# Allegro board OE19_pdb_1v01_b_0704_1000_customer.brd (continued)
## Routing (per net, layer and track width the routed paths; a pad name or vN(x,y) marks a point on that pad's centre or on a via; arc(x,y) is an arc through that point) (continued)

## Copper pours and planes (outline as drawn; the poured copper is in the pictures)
GND on TOP (solid shape): 104.33,152.48 50.66,152.48 50.66,152.99 104.33,152.99
GND on TOP (solid shape): 157.33,152.48 114.59,152.48 114.59,152.99 157.33,152.99
GND on TOP (solid shape): 21.02,58 20.43,56.57 19,55.98 2,55.98 1.3,55.7 1.02,55 1.02,18.22 0.51,18.22 0.51,55 0.94,56.05 2,56.49 19,56.49 20.07,56.93 20.51,58 20.51,106.37 21.02,106.37
GND on TOP (solid shape): 41.02,134.5 40.42,133.07 39,132.48 22,132.48 21.3,132.2 21.02,131.5 21.02,115.91 20.51,115.91 20.51,131.5 20.94,132.56 22,132.99 39,132.99 40.07,133.43 40.51,134.5 40.51,147.73 41.02,147.73
GND on TOP (solid shape): 199.5,152.99 199.85,152.85 199.99,152.5 199.99,151.5 200.43,150.43 201.5,149.99 205.5,149.99 206.55,149.56 206.99,148.5 206.99,126.5 206.55,125.44 205.5,125.01 196.5,125.01 195.43,124.57 194.99,123.5 194.99,2 194.55,0.94 193.5,0.51 193.42,0.51 193.42,1.02 193.5,1.02 194.2,1.3 194.48,2 194.48,123.5 195.07,124.93 196.5,125.52 205.5,125.52 206.2,125.8 206.48,126.5 206.48,148.5 206.2,149.2 205.5,149.48 201.5,149.48 200.07,150.07 199.48,151.5 199.48,152.48 167.68,152.48 167.68,152.99
GND on BOTTOM (solid shape): 104.33,152.48 68.44,152.48 68.44,152.99 104.33,152.99
GND on BOTTOM (solid shape): 157.33,152.48 114.59,152.48 114.59,152.99 157.33,152.99
GND on BOTTOM (solid shape): 21.02,58 20.43,56.57 19,55.98 2,55.98 1.3,55.7 1.02,55 1.02,18.22 0.51,18.22 0.51,55 0.94,56.05 2,56.49 19,56.49 20.07,56.93 20.51,58 20.51,106.37 21.02,106.37
GND on BOTTOM (solid shape): 41.02,134.5 40.42,133.07 39,132.48 22,132.48 21.3,132.2 21.02,131.5 21.02,115.91 20.51,115.91 20.51,131.5 20.94,132.56 22,132.99 39,132.99 40.07,133.43 40.51,134.5 40.51,147.74 41.02,147.74
GND on BOTTOM (solid shape): 199.5,152.99 199.85,152.85 199.99,152.5 199.99,151.5 200.43,150.43 201.5,149.99 205.5,149.99 206.55,149.56 206.99,148.5 206.99,126.5 206.55,125.44 205.5,125.01 196.5,125.01 195.43,124.57 194.99,123.5 194.99,2 194.55,0.94 193.5,0.51 193.42,0.51 193.42,1.02 193.5,1.02 194.2,1.3 194.48,2 194.48,123.5 195.07,124.93 196.5,125.52 205.5,125.52 206.2,125.8 206.48,126.5 206.48,148.5 206.2,149.2 205.5,149.48 201.5,149.48 200.07,150.07 199.48,151.5 199.48,152.48 167.68,152.48 167.68,152.99
GND on BOTTOM (solid shape): outline of 5859 points within 1.28,6.81 154.2,152.18
GND on GND (solid shape): outline of 2787 points within 0.51,0.51 206.99,152.99
GND on IN1 (solid shape): 104.33,152.48 68.44,152.48 68.44,152.99 104.33,152.99
GND on IN1 (solid shape): 157.33,152.48 114.59,152.48 114.59,152.99 157.33,152.99
GND on IN1 (solid shape): 21.02,58 20.43,56.57 19,55.98 2,55.98 1.3,55.7 1.02,55 1.02,18.22 0.51,18.22 0.51,55 0.94,56.05 2,56.49 19,56.49 20.07,56.93 20.51,58 20.51,106.37 21.02,106.37
GND on IN1 (solid shape): 41.02,134.5 40.42,133.07 39,132.48 22,132.48 21.3,132.2 21.02,131.5 21.02,115.91 20.51,115.91 20.51,131.5 20.94,132.56 22,132.99 39,132.99 40.07,133.43 40.51,134.5 40.51,147.77 41.02,147.77
GND on IN1 (solid shape): 199.5,152.99 199.85,152.85 199.99,152.5 199.99,151.5 200.43,150.43 201.5,149.99 205.5,149.99 206.55,149.56 206.99,148.5 206.99,126.5 206.55,125.44 205.5,125.01 196.5,125.01 195.43,124.57 194.99,123.5 194.99,2 194.55,0.94 193.5,0.51 193.42,0.51 193.42,1.02 193.5,1.02 194.2,1.3 194.48,2 194.48,123.5 195.07,124.93 196.5,125.52 205.5,125.52 206.2,125.8 206.48,126.5 206.48,148.5 206.2,149.2 205.5,149.48 201.5,149.48 200.07,150.07 199.48,151.5 199.48,152.48 167.68,152.48 167.68,152.99
GND on IN1 (solid shape): outline of 8850 points within 2.05,7.09 163,151.96
GND on IN2 (solid shape): 104.33,152.48 68.44,152.48 68.44,152.99 104.33,152.99
GND on IN2 (solid shape): 157.33,152.48 114.59,152.48 114.59,152.99 157.33,152.99
GND on IN2 (solid shape): 21.02,58 20.43,56.57 19,55.98 2,55.98 1.3,55.7 1.02,55 1.02,18.22 0.51,18.22 0.51,55 0.94,56.05 2,56.49 19,56.49 20.07,56.93 20.51,58 20.51,106.37 21.02,106.37
GND on IN2 (solid shape): 41.02,134.5 40.42,133.07 39,132.48 22,132.48 21.3,132.2 21.02,131.5 21.02,115.91 20.51,115.91 20.51,131.5 20.94,132.56 22,132.99 39,132.99 40.07,133.43 40.51,134.5 40.51,147.78 41.02,147.78
GND on IN2 (solid shape): 199.5,152.99 199.85,152.85 199.99,152.5 199.99,151.5 200.43,150.43 201.5,149.99 205.5,149.99 206.55,149.56 206.99,148.5 206.99,126.5 206.55,125.44 205.5,125.01 196.5,125.01 195.43,124.57 194.99,123.5 194.99,2 194.55,0.94 193.5,0.51 193.42,0.51 193.42,1.02 193.5,1.02 194.2,1.3 194.48,2 194.48,123.5 195.07,124.93 196.5,125.52 205.5,125.52 206.2,125.8 206.48,126.5 206.48,148.5 206.2,149.2 205.5,149.48 201.5,149.48 200.07,150.07 199.48,151.5 199.48,152.48 167.68,152.48 167.68,152.99
GND on GND1 (solid shape): outline of 2787 points within 0.51,0.51 206.99,152.99
GND on TOP: 129.05,151.42 132.48,151.42 132.95,150.95 132.95,140.99 132.48,140.52 129,140.52 128.2,141.32 128.2,150.58
GND on TOP: 147.04,151.42 149.96,151.42 150.76,150.63 150.76,141.09 150.19,140.52 146.67,140.52 146.34,140.85 146.34,150.72
GND on TOP: 75.68,151.42 79.11,151.42 79.77,150.77 79.77,140.96 79.43,140.62 75.39,140.62 75.11,140.9 75.11,150.86
GND on TOP: 57.68,151.42 61.11,151.42 61.77,150.77 61.77,140.96 61.43,140.62 57.39,140.62 57.11,140.9 57.11,150.86
GND on TOP: 93.67,151.42 97.24,151.42 97.85,150.81 97.85,141.17 97.32,140.64 93.78,140.64 93.3,141.13 93.3,151.05
P3V3_RMC_STBY on TOP: 149.22,23.84 148.28,24.78 145.11,24.78 144.93,24.59 144.93,24.15 145.43,23.65 147.33,23.65 147.47,23.51 147.47,21.88 147.26,21.67 143.74,21.67 129.06,36.35 129.06,78.51 133.55,83 167.21,83 167.79,82.41 167.79,71.33 167.63,71.17 160.12,71.17 160.03,71.26 160.03,72.07 160.31,72.35 160.59,72.35 160.84,72.6 160.84,73.92 160.66,74.1 160.19,74.1 159.97,73.89 159.97,72.53 159.86,72.42 151.78,72.42 148.91,75.29 140.88,75.29 140.71,75.12 140.71,74.41 141.1,74.01 142.63,74.01 142.76,73.88 142.76,73.19 142.58,73.01 141.01,73.01 140.93,72.93 140.93,72.11 141.11,71.93 142.52,71.93 142.73,71.73 142.73,69.98 142.59,69.85 142.07,69.85 141.6,69.37 141.6,68.71 149.36,60.94 149.36,32.11 149.56,31.92 149.93,31.92 150.23,31.62 150.23,29.86 150.04,29.66 148.7,29.66 148.51,29.47 148.51,26.98 149.6,25.88 150.11,25.88 150.29,25.7 150.29,23.95 150.18,23.84
P3V3_RMC_STBY on IN1: 152.66,82.87 155.86,82.87 156.29,82.44 156.29,23.83 156.27,23.82 163.67,16.42 163.67,4.68 164.12,4.23 164.64,4.23 164.93,3.94 164.93,2.75 164.78,2.6 163.49,2.6 162.79,3.29 162.79,5.68 160.76,7.7 160.76,15.51 152.11,24.17 152.11,82.32
P3V3_RMC_STBY on VCC1: 161.75,49.31 161.75,147.06 163.99,147.43 165.02,149.46 165.02,150.13 165.07,150.46 165.23,150.75 165.73,151.57 165.98,152.48 199.48,152.48 199.48,151.5 200.07,150.07 201.5,149.48 205.5,149.48 206.2,149.2 206.48,148.5 206.48,126.5 206.2,125.8 205.5,125.52 196.5,125.52 195.07,124.93 194.48,123.5 194.48,49.31 ; 22 cut-outs
P12V_PSU on IN2 (solid shape): outline of 10114 points within 2.05,7.09 163,151.96
P12V_PSU on TOP: 24.08,12.14 22.91,13.31 22.91,97.25 31.19,105.53 31.19,129.95 32.96,131.72 39.78,131.72 41.24,133.18 41.24,143.49 42.06,144.3 48.6,144.3 50.58,146.28 50.58,151.38 51.45,152.25 56.76,152.25 56.85,152.16 56.85,140.8 57.28,140.37 61.55,140.37 62.02,140.84 62.02,150.9 63.37,152.25 74.08,152.25 74.27,152.06 74.27,140.51 74.8,139.97 79.83,139.97 80.47,140.61 80.47,151 82.44,152.98 90.99,152.98 92.45,151.52 92.45,141.02 93.38,140.09 110.38,140.09 114.6,135.87 117.21,135.87 119.84,138.5 119.84,151.94 120.87,152.98 125.57,152.98 127.45,151.1 127.45,140.88 128.63,139.7 133.65,139.7 134.31,140.36 134.31,151.57 135.72,152.98 143.61,152.98 145.59,151 145.59,140.61 146.38,139.82 154.08,139.82 155.41,138.5 155.41,85.53 154.58,84.7 132.42,84.7 126.88,79.15 126.88,21.17 126.88,21.16 126.88,12.77 126.34,12.23 102.87,12.23 102.23,12.86 102.23,21.12 86.61,36.75 55.56,36.75 49.77,30.95 49.77,21.21 48.91,20.35 48.91,18.68 48.37,18.14 48.37,13.04 47.47,12.14
P12V_PSU on VCC: 2,7.02 1.3,7.3 1.02,8 1.02,55 1.3,55.7 2,55.98 19,55.98 20.43,56.57 21.02,58 21.02,131.5 21.3,132.2 22,132.48 40.57,132.48 41.16,133.08 41.16,143.58 42.17,144.59 48.3,144.59 50.35,146.64 50.35,152.39 50.44,152.48 106.02,152.48 106.27,151.57 106.77,150.75 106.93,150.46 106.98,150.13 106.98,149.46 109.5,146.94 112.02,149.46 112.02,150.13 112.07,150.46 112.23,150.75 112.73,151.57 112.98,152.48 159.02,152.48 159.27,151.57 159.77,150.75 159.93,150.46 159.98,150.13 159.98,149.46 162.5,146.94 165.02,149.46 165.02,150.13 165.07,150.46 165.23,150.75 165.73,151.57 165.98,152.48 199.48,152.48 199.48,151.5 200.07,150.07 201.5,149.48 205.5,149.48 206.2,149.2 206.48,148.5 206.48,126.5 206.2,125.8 205.5,125.52 196.5,125.52 195.07,124.93 194.48,123.5 194.48,49.31 152.38,49.31 128.05,24.98 128.05,13.18 127.55,12.68 83.26,12.68 82.5,13.45 82.5,16.15 81.11,17.54 51.21,17.54 49.32,15.65 49.32,7.02 ; 29 cut-outs
P12V_PSU on VCC1: 2,7.02 1.3,7.3 1.02,8 1.02,55 1.3,55.7 2,55.98 19,55.98 20.43,56.57 21.02,58 21.02,131.5 21.3,132.2 22,132.48 39.97,132.48 41.12,133.63 41.12,144.58 41.2,144.66 47.17,144.66 50.42,147.91 50.42,152.12 50.79,152.48 106.02,152.48 106.27,151.57 106.77,150.75 106.93,150.46 106.98,150.13 106.98,149.46 109.5,146.94 112.02,149.46 112.02,150.13 112.07,150.46 112.23,150.75 112.73,151.57 112.98,152.48 159.02,152.48 159.27,151.57 159.77,150.75 159.93,150.46 159.98,150.13 159.98,149.46 160.32,148.2 161.25,147.28 161.25,49.31 152.34,49.31 128.05,25.02 128.05,13.18 127.55,12.68 83.26,12.68 82.5,13.45 82.5,16.15 81.11,17.54 51.21,17.54 49.32,15.65 49.32,7.02 ; 7 cut-outs
P12V_PSU_STBY on VCC: 164.5,1.02 163.8,1.3 163.52,2 163.52,5 162.93,6.43 161.5,7.02 49.82,7.02 49.82,15.44 51.42,17.03 80.9,17.03 81.99,15.94 81.99,13.24 83.05,12.17 127.76,12.17 128.56,12.97 128.56,24.77 152.59,48.8 194.48,48.8 194.48,2 194.2,1.3 193.5,1.02 ; 22 cut-outs
P12V_PSU_STBY on VCC1: 164.5,1.02 163.8,1.3 163.52,2 163.52,5 162.93,6.43 161.5,7.02 49.82,7.02 49.82,15.44 51.42,17.03 80.9,17.03 81.99,15.94 81.99,13.24 83.05,12.17 127.76,12.17 128.56,12.97 128.56,24.81 152.55,48.8 194.48,48.8 194.48,2 194.2,1.3 193.5,1.02 ; 22 cut-outs
TGND on GND: 219.44,1.13 218.27,-0.03 198.93,-0.03 197.41,1.49 197.41,108.01 196.96,108.46 196.01,108.46 196.01,109.16 196.91,109.16 197.47,109.72 197.47,121.24 198.75,122.52 208.2,122.52 209.47,123.79 209.47,317.55 210.86,318.95 218.12,318.95 219.44,317.63
TGND on VCC: 199.86,0.2 197.67,2.38 197.67,115.1 196.52,115.1 196.52,116.85 197.7,116.85 198.2,117.35 198.2,120.97 199.49,122.27 208.37,122.27 209.6,123.5 209.6,317.02 211.32,318.74 217.44,318.74 219.41,316.78 219.41,2.38 217.23,0.2 ; 8 cut-outs
TGND on VCC1: 199.86,0.2 197.67,2.38 197.67,116.85 197.7,116.85 198.2,117.35 198.2,120.97 199.49,122.27 208.37,122.27 209.6,123.5 209.6,317.02 211.32,318.74 217.44,318.74 219.41,316.78 219.41,2.38 217.23,0.2 ; 8 cut-outs
TGND on GND1: 198.93,-0.03 197.41,1.49 197.41,108.01 196.96,108.46 196.01,108.46 196.01,109.16 196.91,109.16 197.47,109.72 197.47,121.24 198.75,122.52 208.2,122.52 209.47,123.79 209.47,317.55 210.86,318.95 218.12,318.95 219.44,317.63 219.44,1.13 218.27,-0.03 ; 24 cut-outs

Small or netless copper shapes (teardrops, artwork), in the pictures only: 3 on TOP, 3 on BOTTOM

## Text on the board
User.Comments: F
Ref Des/Silkscreen Top: PSU1 | PSU2
User.43: GOLD:RECOMMENDED DRILL SIZE FOR 0.745MM FINISHED PTH IS 0.81-0.86MM(0.85MM DRILL) | IMMERSION TIN/IMMERSION SILVER/COPPER:RECOMMENDED DRILL SIZE FOR 0.75MM FINISHED PTH IS 0.81-0.86MM(0.85MM DRILL). | TIN-LEAD:RECOMMENDED DRILL SIZE FOR 0.725MM FINISHED PTH IS 0.81-0.86MM(0.85MM DRILL) | (0.4MM FINISH PTH- DRILL TOLERANCE FOR TIN LEAD 0.47-0.51MM; COPPER OSP/TIN/SILVER 0.44-0.5MM) | NON-MARK:RECOMMENDED DRILL SIZE FOR 0.4MM FINISHED PTH IS 0.5MM METRIC DRILL OR #77 ENGLISH DRILL. | O:RECOMMENDED DRILL SIZE FOR 0.5MM FINISHED PTH IS 0.6MM METRIC DRILL OR #74 ENGLISH DRILL. | (0.5MM FINISH PTH- DRILL TOLERANCE FOR TIN LEAD 0.57-0.61MM; COPPER OSP/TIN/SILVER 0.54-0.6MM)
User.45: FIGURE | SIZE | 10.0 | 15.74 | 19.68 | 29.52 | 44.0 | 107.0 | 119.0 | 140.0 | 146.0 | 204.0 | 221.0 | 39.0 | 85.0 | 87.0 | 125.0 | DRILL CHART: TOP to BOTTOM | ALL UNITS ARE IN MILS | TOLERANCE | +0.0/-10.0 | +1.96/-1.96 | +3.0/-3.0 | +3.0/-0.0 | +2.0/-2.0 | +2.0/-0.0 | PLATED | NON-PLATED | QTY | 38 | 570 | 154 | 66 | 80 | 120 | 2 | 9 | 1 | 5 | 4 | 3
